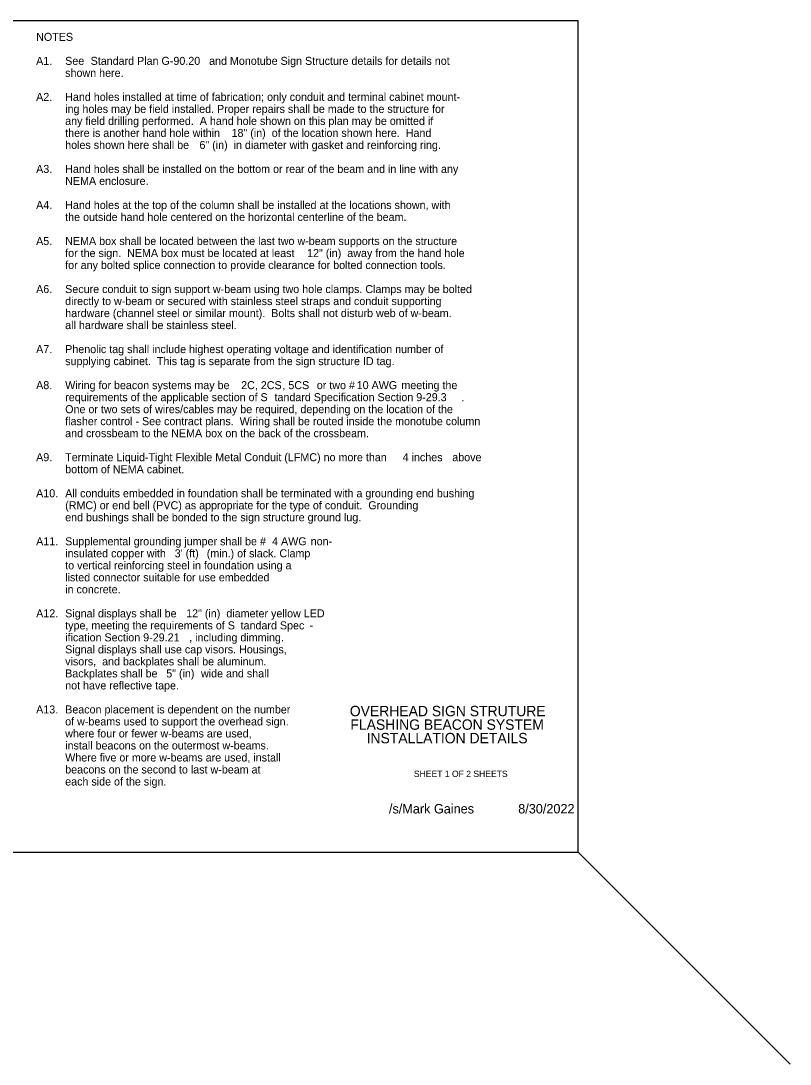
# Model space of a CAD drawing. Extents: x 99862 to 103680, y 99470 to 105076.
# Drawn here: x 101760 to 103680, y 99470 to 102076 of the extents above; entities that cross this region are included whole.
import ezdxf

# ---------------------------------------------------------------- set-up
doc = ezdxf.new("R2010")
doc.units = 0
for name, color, linetype in [('Level 1', 7, 'Continuous'), ('Level 15', 7, 'Continuous'), ('Level 20', 7, 'Continuous'), ('Level 60', 7, 'Continuous'), ('Level 62', 7, 'Continuous')]:
    doc.layers.add(name, color=color, linetype=linetype)

msp = doc.modelspace()

# ---------------------------------------------------------------- linework, layer by layer
at = {"layer": 'Level 1'}
msp.add_line((103150, 100000), (103680.3, 99469.7), dxfattribs=at)
msp.add_lwpolyline([(99862, 99999.5), (103151, 99999.5), (103151, 102075.5), (99862, 102075.5)], close=True, dxfattribs=at)
at = {"layer": 'Level 60'}
msp.add_line((103151, 102075.5), (103151, 102075.5), dxfattribs=at)

# ---------------------------------------------------------------- texts
at = {"layer": 'Level 15'}
for s, height, p in [('/s/Mark Gaines', 23.622, (102678.9, 100095.8)), ('8/30/2022', 23.62, (103001.6, 100095.8))]:
    msp.add_text(s, height=height, dxfattribs=at).set_placement(p)
at = {"layer": 'Level 20'}
for s, p in [('NOTES', (101798.2, 102025.6)), ('A1.', (101798.2, 101965.6)), ('See ', (101870.7, 101965.6)), ('Standard Plan G-90.20', (101934.2, 101965.6)), (' and Monotube Sign Structure details for details not ', (102222.5, 101965.6)), ('shown here.', (101870.7, 101935.6)), ('A2.', (101798.2, 101875.6)), ('Hand holes installed at time of fabrication; only conduit and terminal cabinet mount-', (101870.7, 101875.6)), ('ing holes may be field installed. Proper repairs shall be made to the structure for ', (101870.7, 101845.6)), ('any field drilling performed.  A hand hole shown on this plan may be omitted if ', (101870.7, 101815.6)), ('there is another hand hole within ', (101870.7, 101785.6)), ('18" (in)', (102286, 101785.6)), (' of the location shown here.  Hand ', (102378.9, 101785.6)), ('holes shown here shall be ', (101870.7, 101755.6)), ('6" (in)', (102205.9, 101755.6)), (' in diameter with gasket and reinforcing ring.', (102283.7, 101755.6)), ('A3.', (101798.2, 101695.6)), ('Hand holes shall be installed on the bottom or rear of the beam and in line with any ', (101870.7, 101695.6)), ('NEMA enclosure.', (101870.7, 101665.6)), ('A4.', (101798.2, 101605.6)), ('Hand holes at the top of the column shall be installed at the locations shown, with ', (101870.7, 101605.6)), ('the outside hand hole centered on the horizontal centerline of the beam.', (101870.7, 101575.6)), ('A5.', (101798.2, 101515.6)), ('NEMA box shall be located between the last two w-beam supports on the structure ', (101870.7, 101515.6)), ('for the sign.  NEMA box must be located at least ', (101870.7, 101485.6)), ('12" (in)', (102474.6, 101485.6)), (' away from the hand hole ', (102567.5, 101485.6)), ('for any bolted splice connection to provide clearance for bolted connection tools.', (101870.7, 101455.6)), ('A6.', (101798.2, 101395.6)), ('Secure conduit to sign support w-beam using two hole clamps. Clamps may be bolted ', (101870.7, 101395.6)), ('directly to w-beam or secured with stainless steel straps and conduit supporting ', (101870.7, 101365.6)), ('hardware (channel steel or similar mount).  Bolts shall not disturb web of w-beam.', (101870.7, 101335.6)), ('all hardware shall be stainless steel.', (101870.7, 101305.6)), ('A7.', (101798.2, 101245.6)), ('Phenolic tag shall include highest operating voltage and identification number of ', (101870.7, 101245.6)), ('supplying cabinet.  This tag is separate from the sign structure ID tag.', (101870.7, 101215.6)), ('A8.', (101798.2, 101155.6)), ('Wiring for beacon systems may be ', (101870.7, 101155.6)), ('2C, 2CS', (102310, 101155.6)), (', ', (102412.7, 101155.6)), ('5CS ', (102427.8, 101155.6)), ('or two #', (102498.8, 101155.6)), ('10 AWG', (102598.4, 101155.6)), (' meeting the', (102702.5, 101155.6)), ('requirements of the applicable section of S', (101870.7, 101125.6)), ('tandard Specification Section 9-29.3', (102393.2, 101125.6)), ('One or two sets of wires/cables may be required, depending on the location of the', (101870.7, 101095.6)), ('.', (102859.6, 101125.6)), ('flasher control - See contract plans.  Wiring shall be routed inside the monotube column', (101870.7, 101065.6)), ('and crossbeam to the NEMA box on the back of the crossbeam.', (101870.7, 101035.6)), ('A9.', (101798.2, 100975.6)), ('Terminate Liquid-Tight Flexible Metal Conduit (LFMC) no more than ', (101870.7, 100975.6)), ('4 inches ', (102713.1, 100975.6)), ('above', (102837, 100975.6)), ('bottom of NEMA cabinet.', (101870.7, 100945.6)), ('A10.', (101798.2, 100885.6)), ('All conduits embedded in foundation shall be terminated with a grounding end bushing ', (101870.7, 100885.6)), ('(RMC) or end bell (PVC) as appropriate for the type of conduit.  Grounding ', (101870.7, 100855.6)), ('end bushings shall be bonded to the sign structure ground lug.', (101870.7, 100825.6)), ('A11.', (101798.2, 100765.6)), ('Supplemental grounding jumper shall be #', (101870.7, 100765.6)), ('4 AWG', (102387.2, 100765.6)), (' non-', (102476.2, 100765.6)), ('insulated copper with ', (101870.7, 100735.6)), ("3' (ft)", (102144, 100735.6)), ('  (min.) of slack. Clamp ', (102209.3, 100735.6)), ('to vertical reinforcing steel in foundation using a ', (101870.7, 100705.6)), ('listed connector suitable for use embedded ', (101870.7, 100675.6)), ('in concrete.', (101870.7, 100645.6)), ('A12.', (101798.2, 100585.6)), ('Signal displays shall be ', (101870.7, 100585.6)), ('12" (in)', (102172.7, 100585.6)), (' diameter yellow LED ', (102265.6, 100585.6)), ('type, meeting the requirements of S', (101870.7, 100555.6)), ('tandard Spec', (102308.6, 100555.6)), ('-', (102480.7, 100555.6)), ('ification Section 9-29.21', (101870.7, 100525.6)), (', including dimming.', (102180.2, 100525.6)), ('Signal displays shall use cap visors. Housings, ', (101870.7, 100495.6)), ('visors,  and backplates shall be aluminum.  ', (101870.7, 100465.6)), ('Backplates shall be ', (101870.7, 100435.6)), ('5" (in) ', (102122.9, 100435.6)), ('wide and shall ', (102209.7, 100435.6)), ('not have reflective tape.', (101870.7, 100405.6)), ('A13.', (101798.2, 100345.6)), ('Beacon placement is dependent on the number ', (101870.7, 100345.6)), ('of w-beams used to support the overhead sign.  ', (101870.7, 100315.6)), ('where four or fewer w-beams are used,', (101870.7, 100285.6)), ('install beacons on the outermost w-beams.  ', (101870.7, 100255.6)), ('Where five or more w-beams are used, install ', (101870.7, 100225.6)), ('beacons on the second to last w-beam at', (101870.7, 100195.6)), ('each side of the sign.', (101870.7, 100165.6))]:
    msp.add_text(s, height=20, dxfattribs=at).set_placement(p)
at = {"layer": 'Level 62'}
for s, height, p in [('OVERHEAD SIGN STRUTURE', 26, (102581.2, 100338.6)), ('FLASHING BEACON SYSTEM', 26, (102582.6, 100304.8)), ('INSTALLATION DETAILS', 26, (102623.1, 100271)), ('SHEET 1 OF 2 SHEETS', 16, (102741.1, 100186.8))]:
    msp.add_text(s, height=height, dxfattribs=at).set_placement(p)

doc.saveas('drawing.dxf')
